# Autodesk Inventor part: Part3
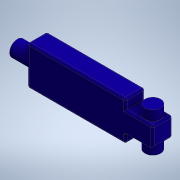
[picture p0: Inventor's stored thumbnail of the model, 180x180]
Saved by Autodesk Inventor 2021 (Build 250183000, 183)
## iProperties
Created: 2025-05
Part Number: Part3
Material: Generic
Document SubType Name: Modeling
Designer: Aaditya
Density: 1 g/cm^3
Appearance: Default
Author: Aaditya
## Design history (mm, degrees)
sketch "Sketch1"
  geometry: L1 (-250, 100)-(250, 100); L2 (250, 100)-(250, -100); L3 (250, -100)-(-250, -100); L4 (-250, -100)-(-250, 100); 1 further point
  constraints: 8 end point, 2 parallel, 1 horizontal, 1 perpendicular
  dimensions: "d0" = 500 distance of L1.start L1.end; "d1" = 200 distance of L3.end L1.start; "d2" = 250 distance from line of point (0, 0) L4; "d3" = 100 distance from line of point (0, 0) L1
extrude "Extrusion1" new body sketch "Sketch1" distance "d4" = 100; taper "d5" = 0 deg
sketch "Sketch2"
  geometry: L1 (34.026, 86.466)-(-66.851, 86.466); L2 (-66.851, 86.466)-(-66.851, 8.807); L3 (-66.851, 8.807)-(34.026, 8.807); L4 (34.026, 8.807)-(34.026, 86.466); L5 (34.026, 86.466)-(-44.286, 86.466); L6 (-44.286, 86.466)-(-44.286, 8.807); L7 (-44.286, 8.807)-(34.026, 8.807); L8 (34.026, 8.807)-(34.026, 86.466); 1 further point
  constraints: 16 end point, 4 parallel, 2 horizontal, 2 perpendicular, 1 point on line
sketch "Sketch3"
  geometry: L1 (250, -100)-(250, 100) reference; L2 (390, 50)-(250, 50); L3 (250, 50)-(250, -50); L4 (250, -50)-(390, -50); L5 (390, -50)-(390, 50); 2 further points
  constraints: 8 end point, 2 parallel, 1 horizontal, 1 perpendicular, 1 point on line
  dimensions: "d6" = 140 distance of L2.start L2.end; "d7" = 100 distance of L4.end L2.start; "d8" = 50 distance from line of point (0, 0) L2
extrude "Extrusion2" join sketch "Sketch3" distance "d9" = 100; taper "d10" = 0 deg
sketch "Sketch4"
  geometry: L1 (140, 0)-(140, -100) reference; L2 (140, -100)-(0, -100) reference; C1 r 40 at (90, -50); 1 further point
  constraints: 1 centre point
  dimensions: "d11" = 80 diameter of C1; "d12" = 50 distance from line of L1 C1.centre; "d13" = 50 distance from line of L2 C1.centre
extrude "Extrusion3" join sketch "Sketch4" distance "d14" = 50; taper "d16" = 0 deg; dims "d15" = 150, "d17" = 0
sketch "Sketch5"
  geometry: L1 (0, 0)-(100, 0) reference; L2 (100, 200)-(100, 0) reference; C1 r 40 at (50, 100); 1 further point
  constraints: 1 centre point
  dimensions: "d18" = 80 diameter of C1; "d19" = 100 distance from line of L1 C1.centre; "d20" = 50 distance from line of L2 C1.centre
extrude "Extrusion4" join sketch "Sketch5" distance "d21" = 100; taper "d22" = 0 deg
fillet "Fillet1" dims "d23" = 10
body "Solid1"
